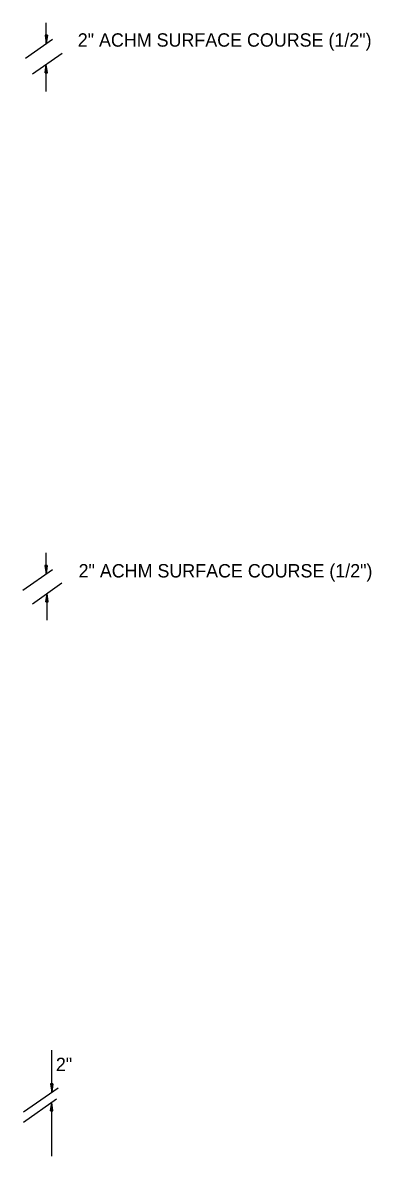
# Model space of a CAD drawing. Extents: x 1926836 to 1933254, y 596317 to 604524.
# Drawn here: x 1929254 to 1929411, y 600250 to 600759 of the extents above; entities that cross this region are included whole.
import ezdxf

# ---------------------------------------------------------------- set-up
doc = ezdxf.new("R2010")
doc.units = 0
doc.layers.add('Default', color=7, linetype='Continuous')

msp = doc.modelspace()

# ---------------------------------------------------------------- linework, layer by layer
at = {"layer": 'Default'}
for p, q in [((1929264.72, 600749.87), (1929264.72, 600759.28)), ((1929255.38, 600743.4), (1929267.56, 600751.83)), ((1929264.19, 600753.6), (1929264.72, 600749.87)), ((1929265.26, 600753.6), (1929264.19, 600753.6)), ((1929264.37, 600753.6), (1929264.72, 600751.12)), ((1929264.37, 600753.6), (1929264.72, 600750.59)), ((1929264.54, 600753.6), (1929264.72, 600752.36)), ((1929264.54, 600753.6), (1929264.72, 600751.83)), ((1929265.26, 600753.6), (1929264.72, 600749.87)), ((1929264.9, 600753.6), (1929264.72, 600752.36)), ((1929265.08, 600753.6), (1929264.72, 600751.12)), ((1929265.26, 600753.6), (1929264.72, 600750.59)), ((1929265.08, 600753.6), (1929264.72, 600751.83)), ((1929264.72, 600753.6), (1929264.72, 600753.07)), ((1929264.9, 600753.6), (1929264.72, 600753.07)), ((1929258.63, 600736.3), (1929271.91, 600745.66)), ((1929264.2, 600736.75), (1929264.73, 600740.48)), ((1929264.2, 600736.75), (1929265.26, 600736.75)), ((1929264.38, 600736.75), (1929264.73, 600739.95)), ((1929264.38, 600736.75), (1929264.73, 600739.23)), ((1929264.55, 600736.75), (1929264.73, 600738.7)), ((1929264.55, 600736.75), (1929264.73, 600737.98)), ((1929264.73, 600728.4), (1929264.73, 600740.48)), ((1929265.26, 600736.75), (1929264.73, 600740.48)), ((1929265.26, 600736.75), (1929264.73, 600739.95)), ((1929265.09, 600736.75), (1929264.73, 600739.23)), ((1929265.09, 600736.75), (1929264.73, 600738.7)), ((1929264.9, 600736.75), (1929264.73, 600737.98)), ((1929264.9, 600736.75), (1929264.73, 600737.46)), ((1929264.73, 600736.75), (1929264.73, 600737.46)), ((1929264.63, 600511.82), (1929264.63, 600521.23)), ((1929254.16, 600504.56), (1929267.47, 600513.78)), ((1929264.1, 600515.55), (1929264.63, 600511.82)), ((1929265.16, 600515.55), (1929264.1, 600515.55)), ((1929264.28, 600515.55), (1929264.63, 600513.06)), ((1929264.28, 600515.55), (1929264.63, 600512.53)), ((1929264.45, 600515.55), (1929264.63, 600514.31)), ((1929264.45, 600515.55), (1929264.63, 600513.78)), ((1929265.16, 600515.55), (1929264.63, 600511.82)), ((1929264.8, 600515.55), (1929264.63, 600514.31)), ((1929264.99, 600515.55), (1929264.63, 600513.06)), ((1929265.16, 600515.55), (1929264.63, 600512.53)), ((1929264.99, 600515.55), (1929264.63, 600513.78)), ((1929264.63, 600515.55), (1929264.63, 600515.02)), ((1929264.8, 600515.55), (1929264.63, 600515.02)), ((1929258.5, 600498.4), (1929271.73, 600507.73)), ((1929264.59, 600499.33), (1929265.12, 600503.07)), ((1929264.77, 600499.33), (1929265.12, 600502.53)), ((1929264.77, 600499.33), (1929265.12, 600501.82)), ((1929265.12, 600490.98), (1929265.12, 600503.07)), ((1929265.65, 600499.33), (1929265.12, 600503.07)), ((1929265.65, 600499.33), (1929265.12, 600502.53)), ((1929265.48, 600499.33), (1929265.12, 600501.82)), ((1929264.59, 600499.33), (1929265.65, 600499.33)), ((1929264.94, 600499.33), (1929265.12, 600501.28)), ((1929264.94, 600499.33), (1929265.12, 600500.57)), ((1929265.48, 600499.33), (1929265.12, 600501.28)), ((1929265.3, 600499.33), (1929265.12, 600500.57)), ((1929265.3, 600499.33), (1929265.12, 600500.05)), ((1929265.12, 600499.33), (1929265.12, 600500.05)), ((1929267.2, 600279.08), (1929267.2, 600297.92)), ((1929266.68, 600282.82), (1929267.2, 600279.08)), ((1929267.74, 600282.82), (1929266.68, 600282.82)), ((1929266.86, 600282.82), (1929267.2, 600280.33)), ((1929266.86, 600282.82), (1929267.2, 600279.8)), ((1929267.02, 600282.82), (1929267.2, 600281.58)), ((1929267.02, 600282.82), (1929267.2, 600281.05)), ((1929267.74, 600282.82), (1929267.2, 600279.08)), ((1929267.38, 600282.82), (1929267.2, 600281.58)), ((1929267.57, 600282.82), (1929267.2, 600280.33)), ((1929267.74, 600282.82), (1929267.2, 600279.8)), ((1929267.57, 600282.82), (1929267.2, 600281.05)), ((1929267.2, 600282.82), (1929267.2, 600282.28)), ((1929267.38, 600282.82), (1929267.2, 600282.28)), ((1929254.5, 600270.23), (1929270.05, 600281.05)), ((1929254.48, 600265.71), (1929269.34, 600276.07)), ((1929266.68, 600270.74), (1929267.2, 600274.48)), ((1929266.86, 600270.74), (1929267.2, 600273.94)), ((1929266.86, 600270.74), (1929267.2, 600273.22)), ((1929267.02, 600270.74), (1929267.2, 600272.69)), ((1929267.2, 600250.31), (1929267.2, 600274.48)), ((1929267.74, 600270.74), (1929267.2, 600274.48)), ((1929267.74, 600270.74), (1929267.2, 600273.94)), ((1929267.57, 600270.74), (1929267.2, 600273.22)), ((1929267.57, 600270.74), (1929267.2, 600272.69)), ((1929266.68, 600270.74), (1929267.74, 600270.74)), ((1929267.02, 600270.74), (1929267.2, 600271.98)), ((1929267.38, 600270.74), (1929267.2, 600271.98)), ((1929267.38, 600270.74), (1929267.2, 600271.46)), ((1929267.2, 600270.74), (1929267.2, 600271.46))]:
    msp.add_line(p, q, dxfattribs=at)

# ---------------------------------------------------------------- texts
for p in [(1929278.87, 600748.51), (1929279.25, 600510.19)]:
    msp.add_text('2" ACHM SURFACE COURSE (1/2")', height=6, dxfattribs=at).set_placement(p)
msp.add_text('2"', height=6, rotation=360, dxfattribs=at).set_placement((1929269.05, 600288.55))

doc.saveas('drawing.dxf')
